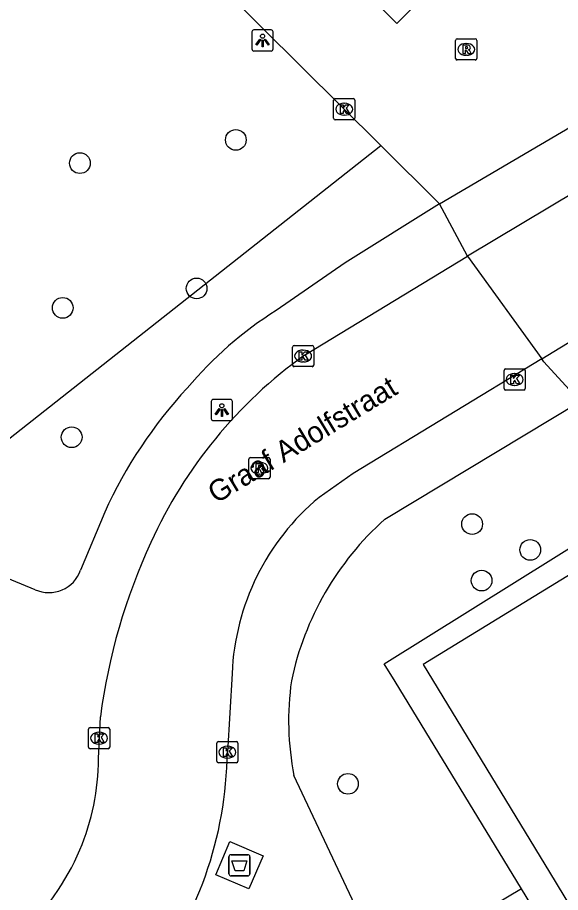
# Model space of a CAD drawing. Extents: x 159961 to 160856, y 382704 to 383353.
# Drawn here: x 160298.19 to 160323.83, y 383013.92 to 383055.21 of the extents above; entities that cross this region are included whole.
import ezdxf

# ---------------------------------------------------------------- set-up
doc = ezdxf.new("R2010")
doc.units = 0
for name, color, linetype in [('IMGEO_Afval_apart_plaats', 7, 'Continuous'), ('IMGEO_Boom', 7, 'Continuous'), ('IMGEO_Groenvoorziening', 7, 'Continuous'), ('IMGEO_Kolk', 7, 'Continuous'), ('IMGEO_Lichtpunt', 7, 'Continuous'), ('IMGEO_Openbare_ruimte_label', 7, 'Continuous'), ('IMGEO_Pand', 7, 'Continuous'), ('IMGEO_Rijbaan_lokaal_open', 7, 'Continuous'), ('IMGEO_Rioolput', 7, 'Continuous'), ('IMGEO_Voetpad_gesloten', 7, 'Continuous'), ('IMGEO_Voetpad_open', 7, 'Continuous')]:
    doc.layers.add(name, color=color, linetype=linetype)

msp = doc.modelspace()

# ---------------------------------------------------------------- linework, layer by layer
at = {"layer": 'IMGEO_Afval_apart_plaats'}
for p, q in [((160308.175, 383014.8), (160308.175, 383015.6)), ((160308.175, 383015.6), (160308.175, 383014.8)), ((160308.275, 383015.7), (160309.065, 383015.7)), ((160309.065, 383015.7), (160308.275, 383015.7)), ((160309.165, 383015.6), (160309.165, 383014.8)), ((160309.165, 383014.8), (160309.165, 383015.6)), ((160309.065, 383014.7), (160308.275, 383014.7)), ((160308.275, 383014.7), (160309.065, 383014.7))]:
    msp.add_line(p, q, dxfattribs=at)
msp.add_lwpolyline([(160308.318, 383015.414), (160309.022, 383015.414), (160308.873, 383014.944), (160308.467, 383014.944), (160308.318, 383015.414)], dxfattribs=at)
for centre, start, end in [((160308.275, 383015.6), 90, 180), ((160308.275, 383015.6), 90, 180), ((160309.065, 383015.6), 0, 90), ((160309.065, 383015.6), 360, 90), ((160308.275, 383014.8), 180, 270), ((160308.275, 383014.8), 180, 270), ((160309.065, 383014.8), 270, 0), ((160309.065, 383014.8), 270, 0)]:
    msp.add_arc(centre, 0.1, start, end, dxfattribs=at)
at = {"layer": 'IMGEO_Boom'}
for centre in [(160308.5, 383049.431), (160301.139, 383048.336), (160306.649, 383042.422), (160300.328, 383041.506), (160300.749, 383035.4), (160319.657, 383031.302), (160322.399, 383030.084), (160320.105, 383028.635), (160313.793, 383019.044)]:
    msp.add_circle(centre, 0.489, dxfattribs=at)
at = {"layer": 'IMGEO_Groenvoorziening'}
for points in [[(160291.641, 383030.493), (160315.353, 383049.161)], [(160321.983, 383014.084), (160316.015, 383023.874), (160315.507, 383024.71), (160327.687, 383032.3)]]:
    msp.add_lwpolyline(points, dxfattribs=at)
at = {"layer": 'IMGEO_Kolk'}
for p, q in [((160313.193, 383051.38), (160314.045, 383051.38)), ((160313.118, 383050.454), (160313.118, 383051.306)), ((160313.606, 383051.16), (160313.631, 383051.16)), ((160314.119, 383051.306), (160314.119, 383050.454)), ((160313.629, 383050.6), (160313.604, 383050.6)), ((160314.045, 383050.38), (160313.193, 383050.38)), ((160311.177, 383038.805), (160311.177, 383039.657)), ((160311.252, 383039.731), (160312.104, 383039.731)), ((160311.665, 383039.511), (160311.69, 383039.511)), ((160312.178, 383039.657), (160312.178, 383038.805)), ((160311.688, 383038.951), (160311.663, 383038.951)), ((160312.104, 383038.731), (160311.252, 383038.731)), ((160321.163, 383037.699), (160321.163, 383038.551)), ((160321.238, 383038.625), (160322.09, 383038.625)), ((160322.164, 383038.551), (160322.164, 383037.699)), ((160321.651, 383038.405), (160321.676, 383038.405)), ((160321.674, 383037.845), (160321.649, 383037.845)), ((160322.09, 383037.625), (160321.238, 383037.625)), ((160301.543, 383020.773), (160301.543, 383021.625)), ((160301.618, 383021.699), (160302.47, 383021.699)), ((160302.544, 383021.625), (160302.544, 383020.773)), ((160302.031, 383021.479), (160302.056, 383021.479)), ((160302.054, 383020.919), (160302.029, 383020.919)), ((160307.601, 383020.112), (160307.601, 383020.964)), ((160307.676, 383021.038), (160308.528, 383021.038)), ((160308.089, 383020.818), (160308.114, 383020.818)), ((160308.602, 383020.964), (160308.602, 383020.112)), ((160302.47, 383020.699), (160301.618, 383020.699)), ((160308.528, 383020.038), (160307.676, 383020.038)), ((160308.112, 383020.258), (160308.087, 383020.258))]:
    msp.add_line(p, q, dxfattribs=at)
for points in [[(160313.193, 383051.38), (160314.045, 383051.38)], [(160313.118, 383050.454), (160313.118, 383051.306)], [(160313.439, 383051.08), (160313.562, 383051.08), (160313.562, 383050.929), (160313.692, 383051.08), (160313.856, 383051.08), (160313.71, 383050.929), (160313.863, 383050.68), (160313.711, 383050.68), (160313.626, 383050.844), (160313.562, 383050.777), (160313.562, 383050.68), (160313.439, 383050.68), (160313.439, 383051.08)], [(160314.119, 383051.306), (160314.119, 383050.454)], [(160314.045, 383050.38), (160313.193, 383050.38)], [(160311.177, 383038.805), (160311.177, 383039.657)], [(160311.252, 383039.731), (160312.104, 383039.731)], [(160311.498, 383039.431), (160311.621, 383039.431), (160311.621, 383039.28), (160311.751, 383039.431), (160311.915, 383039.431), (160311.769, 383039.28), (160311.922, 383039.031), (160311.77, 383039.031), (160311.685, 383039.195), (160311.621, 383039.128), (160311.621, 383039.031), (160311.498, 383039.031), (160311.498, 383039.431)], [(160312.178, 383039.657), (160312.178, 383038.805)], [(160312.104, 383038.731), (160311.252, 383038.731)], [(160321.163, 383037.699), (160321.163, 383038.551)], [(160321.238, 383038.625), (160322.09, 383038.625)], [(160322.164, 383038.551), (160322.164, 383037.699)], [(160321.484, 383038.325), (160321.607, 383038.325), (160321.607, 383038.174), (160321.737, 383038.325), (160321.901, 383038.325), (160321.755, 383038.174), (160321.908, 383037.925), (160321.756, 383037.925), (160321.671, 383038.089), (160321.607, 383038.022), (160321.607, 383037.925), (160321.484, 383037.925), (160321.484, 383038.325)], [(160322.09, 383037.625), (160321.238, 383037.625)], [(160301.543, 383020.773), (160301.543, 383021.625)], [(160301.618, 383021.699), (160302.47, 383021.699)], [(160302.544, 383021.625), (160302.544, 383020.773)], [(160301.864, 383021.399), (160301.987, 383021.399), (160301.987, 383021.248), (160302.117, 383021.399), (160302.281, 383021.399), (160302.135, 383021.248), (160302.288, 383020.999), (160302.136, 383020.999), (160302.051, 383021.163), (160301.987, 383021.096), (160301.987, 383020.999), (160301.864, 383020.999), (160301.864, 383021.399)], [(160307.601, 383020.112), (160307.601, 383020.964)], [(160307.676, 383021.038), (160308.528, 383021.038)], [(160308.602, 383020.964), (160308.602, 383020.112)], [(160302.47, 383020.699), (160301.618, 383020.699)], [(160307.922, 383020.738), (160308.045, 383020.738), (160308.045, 383020.587), (160308.175, 383020.738), (160308.339, 383020.738), (160308.193, 383020.587), (160308.346, 383020.338), (160308.194, 383020.338), (160308.109, 383020.502), (160308.045, 383020.435), (160308.045, 383020.338), (160307.922, 383020.338), (160307.922, 383020.738)], [(160308.528, 383020.038), (160307.676, 383020.038)]]:
    msp.add_lwpolyline(points, dxfattribs=at)
for centre, start, end in [((160313.195, 383051.304), 91.552, 178.448), ((160313.195, 383051.304), 91.552, 178.448), ((160314.043, 383051.304), 1.552, 88.448), ((160314.043, 383051.304), 1.552, 88.448), ((160313.195, 383050.456), 181.552, 268.448), ((160313.195, 383050.456), 181.552, 268.448), ((160314.043, 383050.456), 271.552, 358.448), ((160314.043, 383050.456), 271.552, 358.448), ((160311.254, 383039.655), 91.552, 178.448), ((160311.254, 383039.655), 91.552, 178.448), ((160312.102, 383039.655), 1.552, 88.448), ((160312.102, 383039.655), 1.552, 88.448), ((160311.254, 383038.807), 181.552, 268.448), ((160311.254, 383038.807), 181.552, 268.448), ((160312.102, 383038.807), 271.552, 358.448), ((160312.102, 383038.807), 271.552, 358.448), ((160321.24, 383038.549), 91.552, 178.448), ((160321.24, 383038.549), 91.552, 178.448), ((160322.088, 383038.549), 1.552, 88.448), ((160322.088, 383038.549), 1.552, 88.448), ((160321.24, 383037.701), 181.552, 268.448), ((160321.24, 383037.701), 181.552, 268.448), ((160322.088, 383037.701), 271.552, 358.448), ((160322.088, 383037.701), 271.552, 358.448), ((160301.62, 383021.623), 91.552, 178.448), ((160301.62, 383021.623), 91.552, 178.448), ((160302.468, 383021.623), 1.552, 88.448), ((160302.468, 383021.623), 1.552, 88.448), ((160301.62, 383020.775), 181.552, 268.448), ((160301.62, 383020.775), 181.552, 268.448), ((160302.468, 383020.775), 271.552, 358.448), ((160302.468, 383020.775), 271.552, 358.448), ((160307.678, 383020.962), 91.552, 178.448), ((160307.678, 383020.962), 91.552, 178.448), ((160308.526, 383020.962), 1.552, 88.448), ((160308.526, 383020.962), 1.552, 88.448), ((160307.678, 383020.114), 181.552, 268.448), ((160307.678, 383020.114), 181.552, 268.448), ((160308.526, 383020.114), 271.552, 358.448), ((160308.526, 383020.114), 271.552, 358.448)]:
    msp.add_arc(centre, 0.0765, start, end, dxfattribs=at)
for centre, major_axis, ratio, start_param, end_param in [((160313.605, 383050.88), (-0.387, 0.002), 0.722429, 4.712389, 7.853982), ((160313.63, 383050.88), (-0.39, 0.002), 0.717154, 1.570796, 4.712389), ((160311.664, 383039.231), (-0.387, 0.002), 0.722429, 4.712389, 7.853982), ((160311.689, 383039.231), (-0.39, 0.002), 0.717154, 1.570796, 4.712389), ((160321.65, 383038.125), (-0.387, 0.002), 0.722429, 4.712389, 7.853982), ((160321.675, 383038.125), (-0.39, 0.002), 0.717154, 1.570796, 4.712389), ((160302.03, 383021.199), (-0.387, 0.002), 0.722429, 4.712389, 7.853982), ((160302.055, 383021.199), (-0.39, 0.002), 0.717154, 1.570796, 4.712389), ((160308.088, 383020.538), (-0.387, 0.002), 0.722429, 4.712389, 7.853982), ((160308.113, 383020.538), (-0.39, 0.002), 0.717154, 1.570796, 4.712389)]:
    msp.add_ellipse(centre, major_axis=major_axis, ratio=ratio, start_param=start_param, end_param=end_param, dxfattribs=at)
at = {"layer": 'IMGEO_Lichtpunt'}
for p, q in [((160310.165, 383054.624), (160309.357, 383054.624)), ((160310.165, 383054.624), (160309.357, 383054.624)), ((160309.263, 383054.529), (160309.263, 383053.722)), ((160309.263, 383054.529), (160309.263, 383053.722)), ((160310.259, 383053.722), (160310.259, 383054.529)), ((160310.259, 383053.722), (160310.259, 383054.529)), ((160309.357, 383053.628), (160310.165, 383053.628)), ((160309.357, 383053.628), (160310.165, 383053.628)), ((160307.34, 383037.087), (160307.34, 383036.28)), ((160307.34, 383037.087), (160307.34, 383036.28)), ((160308.242, 383037.182), (160307.434, 383037.182)), ((160308.242, 383037.182), (160307.434, 383037.182)), ((160308.336, 383036.28), (160308.336, 383037.087)), ((160308.336, 383036.28), (160308.336, 383037.087)), ((160307.434, 383036.186), (160308.242, 383036.186)), ((160307.434, 383036.186), (160308.242, 383036.186))]:
    msp.add_line(p, q, dxfattribs=at)
for points in [[(160309.637, 383054.193), (160309.676, 383054.165), (160309.488, 383053.903), (160309.45, 383053.93), (160309.637, 383054.193)], [(160309.739, 383054.145), (160309.786, 383054.145), (160309.786, 383053.823), (160309.739, 383053.823), (160309.739, 383054.145)], [(160309.849, 383054.165), (160309.887, 383054.192), (160310.074, 383053.93), (160310.035, 383053.902), (160309.849, 383054.165)], [(160307.714, 383036.751), (160307.753, 383036.723), (160307.565, 383036.461), (160307.527, 383036.488), (160307.714, 383036.751)], [(160307.816, 383036.703), (160307.863, 383036.703), (160307.863, 383036.381), (160307.816, 383036.381), (160307.816, 383036.703)], [(160307.926, 383036.723), (160307.964, 383036.75), (160308.151, 383036.488), (160308.112, 383036.46), (160307.926, 383036.723)]]:
    msp.add_lwpolyline(points, dxfattribs=at)
for centre in [(160309.762, 383054.327), (160307.839, 383036.885)]:
    msp.add_circle(centre, 0.0994, dxfattribs=at)
for centre, start, end in [((160309.357, 383054.529), 90, 180), ((160309.357, 383054.529), 90, 180), ((160310.165, 383054.529), 0, 90), ((160310.165, 383054.529), 0, 90), ((160309.357, 383053.722), 180, 270), ((160309.357, 383053.722), 180, 270), ((160310.165, 383053.722), 270, 0), ((160310.165, 383053.722), 270, 360), ((160307.434, 383037.087), 90, 180), ((160307.434, 383037.087), 90, 180), ((160308.242, 383037.087), 0, 90), ((160308.242, 383037.087), 0, 90), ((160307.434, 383036.28), 180, 270), ((160307.434, 383036.28), 180, 270), ((160308.242, 383036.28), 270, 0), ((160308.242, 383036.28), 270, 360)]:
    msp.add_arc(centre, 0.0946, start, end, dxfattribs=at)
at = {"layer": 'IMGEO_Pand'}
for points in [[(160318.515, 383057.34), (160316.097, 383054.928), (160312.177, 383058.858)], [(160354.153, 382986.675), (160346.052, 383000), (160327.335, 383030.788), (160317.351, 383024.674), (160323.309, 383014.872), (160325.073, 383011.971), (160332.352, 383000), (160336.511, 382993.16), (160338.283, 382990.248), (160344.157, 382980.593)]]:
    msp.add_lwpolyline(points, dxfattribs=at)
at = {"layer": 'IMGEO_Rijbaan_lokaal_open'}
for points in [[(160300.321, 383064.084), (160315.353, 383049.161)], [(160318.121, 383046.413), (160325.142, 383050.537)], [(160315.353, 383049.161), (160318.121, 383046.413)], [(160327.187, 383048.566), (160319.443, 383043.946)], [(160311.735, 383039.271), (160319.443, 383043.946)], [(160319.443, 383043.946), (160322.951, 383039.108)], [(160322.951, 383039.108), (160326.784, 383041.444)], [(160322.951, 383039.108), (160314.042, 383033.682), (160312.427, 383032.562)], [(160308.323, 383024.255), (160308.101, 383020.542)], [(160302.022, 383020.233), (160302.106, 383022.209)]]:
    msp.add_lwpolyline(points, dxfattribs=at)
for centre, radius, start, end in [((160324.659, 383021.288), 22.145, 125.7046, 155.5988), ((160319.778, 383023.763), 11.466, 129.8766, 177.5409), ((160330.094, 383018.553), 28.226, 155.0998, 172.5574), ((160289.815, 383020.776), 18.287, 321.9859, 359.2657), ((160290.76, 383020.297), 11.262, 337.171, 359.6721), ((160289.455, 383021.029), 12.75, 291.9638, 336.4148)]:
    msp.add_arc(centre, radius, start, end, dxfattribs=at)
at = {"layer": 'IMGEO_Rioolput'}
for p, q in [((160318.952, 383054.203), (160319.804, 383054.203)), ((160318.877, 383053.277), (160318.877, 383054.129)), ((160319.365, 383053.983), (160319.39, 383053.983)), ((160319.878, 383054.129), (160319.878, 383053.277)), ((160319.388, 383053.423), (160319.363, 383053.423)), ((160319.804, 383053.203), (160318.952, 383053.203)), ((160309.188, 383034.442), (160310.04, 383034.442)), ((160309.113, 383033.516), (160309.113, 383034.368)), ((160309.601, 383034.222), (160309.626, 383034.222)), ((160310.114, 383034.368), (160310.114, 383033.516)), ((160309.624, 383033.662), (160309.599, 383033.662)), ((160310.04, 383033.442), (160309.188, 383033.442))]:
    msp.add_line(p, q, dxfattribs=at)
for points in [[(160318.952, 383054.203), (160319.804, 383054.203)], [(160318.877, 383053.277), (160318.877, 383054.129)], [(160319.466, 383053.901), (160319.214, 383053.903), (160319.214, 383053.503)], [(160319.392, 383053.822), (160319.338, 383053.822), (160319.338, 383053.741)], [(160319.878, 383054.129), (160319.878, 383053.277)], [(160319.214, 383053.503), (160319.338, 383053.503), (160319.338, 383053.665), (160319.349, 383053.665)], [(160319.338, 383053.741), (160319.39, 383053.741)], [(160319.396, 383053.636), (160319.467, 383053.503), (160319.607, 383053.503), (160319.542, 383053.629)], [(160319.804, 383053.203), (160318.952, 383053.203)], [(160309.188, 383034.442), (160310.04, 383034.442)], [(160309.113, 383033.516), (160309.113, 383034.368)], [(160309.702, 383034.14), (160309.45, 383034.142), (160309.45, 383033.742)], [(160309.628, 383034.061), (160309.574, 383034.061), (160309.574, 383033.98)], [(160309.574, 383033.98), (160309.626, 383033.98)], [(160310.114, 383034.368), (160310.114, 383033.516)], [(160309.45, 383033.742), (160309.574, 383033.742), (160309.574, 383033.904), (160309.585, 383033.904)], [(160309.632, 383033.875), (160309.703, 383033.742), (160309.843, 383033.742), (160309.778, 383033.868)], [(160310.04, 383033.442), (160309.188, 383033.442)]]:
    msp.add_lwpolyline(points, dxfattribs=at)
for centre, radius, start, end in [((160318.954, 383054.127), 0.0765, 91.552, 178.448), ((160318.954, 383054.127), 0.0765, 91.552, 178.448), ((160319.802, 383054.127), 0.0765, 1.552, 88.448), ((160319.802, 383054.127), 0.0765, 1.552, 88.448), ((160319.398, 383053.726), 0.0964, 77.0061, 93.1865), ((160319.412, 383053.783), 0.0378, 276.6634, 79.6772), ((160319.465, 383053.791), 0.109, 350.3612, 89.416), ((160319.348, 383053.612), 0.0533, 26.0293, 88.6989), ((160319.374, 383053.93), 0.19, 274.7715, 282.9687), ((160319.463, 383053.791), 0.112, 277.5842, 350.9817), ((160319.447, 383053.576), 0.108, 29.5134, 73.7905), ((160318.954, 383053.279), 0.0765, 181.552, 268.448), ((160318.954, 383053.279), 0.0765, 181.552, 268.448), ((160319.802, 383053.279), 0.0765, 271.552, 358.448), ((160319.802, 383053.279), 0.0765, 271.552, 358.448), ((160309.19, 383034.366), 0.0765, 91.552, 178.448), ((160309.19, 383034.366), 0.0765, 91.552, 178.448), ((160310.038, 383034.366), 0.0765, 1.552, 88.448), ((160310.038, 383034.366), 0.0765, 1.552, 88.448), ((160309.61, 383034.169), 0.19, 274.7715, 282.9687), ((160309.634, 383033.965), 0.0964, 77.0061, 93.1865), ((160309.648, 383034.022), 0.0378, 276.6634, 79.6772), ((160309.701, 383034.03), 0.109, 350.3612, 89.416), ((160309.699, 383034.03), 0.112, 277.5842, 350.9817), ((160309.584, 383033.851), 0.0533, 26.0293, 88.6989), ((160309.683, 383033.815), 0.108, 29.5134, 73.7905), ((160309.19, 383033.518), 0.0765, 181.552, 268.448), ((160309.19, 383033.518), 0.0765, 181.552, 268.448), ((160310.038, 383033.518), 0.0765, 271.552, 358.448), ((160310.038, 383033.518), 0.0765, 271.552, 358.448)]:
    msp.add_arc(centre, radius, start, end, dxfattribs=at)
for centre, major_axis, ratio, start_param, end_param in [((160319.364, 383053.703), (-0.387, 0.002), 0.722429, 4.712389, 7.853982), ((160319.389, 383053.703), (-0.39, 0.002), 0.717154, 1.570796, 4.712389), ((160309.6, 383033.942), (-0.387, 0.002), 0.722429, 4.712389, 7.853982), ((160309.625, 383033.942), (-0.39, 0.002), 0.717154, 1.570796, 4.712389)]:
    msp.add_ellipse(centre, major_axis=major_axis, ratio=ratio, start_param=start_param, end_param=end_param, dxfattribs=at)
at = {"layer": 'IMGEO_Voetpad_gesloten'}
msp.add_lwpolyline([(160309.119, 383014.085), (160307.554, 383014.751), (160308.22, 383016.315), (160309.785, 383015.649), (160309.119, 383014.085)], dxfattribs=at)
at = {"layer": 'IMGEO_Voetpad_open'}
for points in [[(160318.121, 383046.413), (160313.666, 383043.625), (160310.401, 383041.379)], [(160319.443, 383043.946), (160318.121, 383046.413)], [(160324.759, 383037.085), (160323.041, 383038.96), (160322.951, 383039.108)], [(160315.53, 383031.527), (160324.759, 383037.085)], [(160302.309, 383031.863), (160301.174, 383029.12)], [(160299.026, 383028.206), (160293.341, 383030.546)], [(160321.983, 383014.084), (160315.562, 383010.268), (160311.246, 383019.431)], [(160323.762, 383011.165), (160321.983, 383014.084)]]:
    msp.add_lwpolyline(points, dxfattribs=at)
for centre, radius, start, end in [((160320.004, 383026.136), 18.016, 122.2101, 139.9797), ((160322.462, 383022.679), 22.147, 137.219, 155.5003), ((160324.951, 383020.997), 14.129, 131.8185, 168.1119), ((160299.674, 383029.664), 1.596, 246.0401, 340.0606), ((160324.438, 383022.028), 13.445, 171.9608, 191.1355)]:
    msp.add_arc(centre, radius, start, end, dxfattribs=at)

# ---------------------------------------------------------------- texts
at = {"layer": 'IMGEO_Openbare_ruimte_label'}
msp.add_text('Graaf Adolfstraat', height=1, rotation=31.2095, dxfattribs=at).set_placement((160307.57, 383032.244))

doc.saveas('drawing.dxf')
